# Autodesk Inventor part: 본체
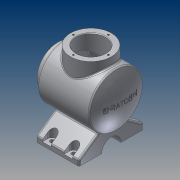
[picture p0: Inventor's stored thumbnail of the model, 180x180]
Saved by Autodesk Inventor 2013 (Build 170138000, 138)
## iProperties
Created: 2017-04
Part Number: 본체
Material: 알루미늄 6061
Document SubType Name: Modeling
Designer: Administrator
Density: 2.71 g/cm^3
Mass: 1670.26 g
Surface Area: 1068.05 cm^2
Volume: 616.331 cm^3
Author: Administrator
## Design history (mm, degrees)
sketch "스케치1"
  geometry: L1 (-62, 82)-(58, 82); L2 (-50, 132)-(46.336, 132); L3 (-50, 132)-(-50, 120); L4 (-50, 120)-(-62, 120); L5 (-62, 120)-(-62, 82); L6 (39.916, 122)-(-40, 122); L7 (-62, 109)-(-40, 109); L8 (-40, 122)-(-40, 109); A1 r 113 centre (-55, 82) between (58, 82) and (46.336, 132); A2 r 103 centre (-55, 82) between (48, 82) and (39.916, 122); 1 further point
  constraints: 16 end point, 4 point on circle, 3 perpendicular, 3 point on line, 2 centre point, 2 parallel, 1 horizontal
  dimensions: "d1" = 120 distance of L1.start L1.end; "d3" = 58 horizontal distance of point (0, 0) L1.end; "d5" = 113 radius of A1; "d6" = 82 vertical distance of point (0, 0) L1.end; "d7" = 100 diameter of L2 L1; "d8" = 108 horizontal distance of L2.start L1.end; "d9" = 76 diameter of L4 L1; "d10" = 10 distance between parallel lines of L6 L2; "d12" = 10 radial gap between concentric circles of A1 A2; "d13" = 54 diameter of L7 L1; "d14" = 22 distance of L7.start L7.end
revolve "회전1" sketch "스케치1" stored, may be unused: angle "d15" = 90 deg
node "작업 평면1"
sketch "스케치2"
  geometry: L1 (-60, -82)-(-60, -72); L2 (60, -82)-(60, -72); L3 (0, -82)-(0, 0); L4 (-60, -72)-(-21.584, -45.101); L5 (60, -72)-(21.584, -45.101); L6 (-60, -82)-(-18, -82); L7 (60, -82)-(18, -82); C1 r 27 at (0, 0) reference; A1 r 50 centre (0, 0) between (-21.584, -45.101) and (21.584, -45.101) reference; A2 r 18 centre (0, -82) between (18, -82) and (-18, -82)
  constraints: 14 end point, 4 point on circle, 3 parallel, 2 horizontal alignment, 1 centre point, 1 coincident, 1 collinear, 1 perpendicular, 1 vertical, 2 other
  dimensions: "d18" = 120 distance of L1.start L2.start; "d20" = 55 deg angle of L1 L4; "d21" = 18 radius of A2; "d98" = 10 distance of L2.start L2.end
extrude "돌출1" join sketch "스케치2" distance "d22" = 80; taper "d23" = 0 deg
node "작업 평면2"
sketch "스케치3"
  geometry: L1 (-38, 60)-(42, 60) reference; L2 (42, 60)-(42, 16.971) reference; L3 (42, 16.971)-(-38, 16.971) reference; L4 (-38, 16.971)-(-38, 60) reference; L5 (42, -60)-(-38, -60) reference; L6 (-38, -60)-(-38, -16.971) reference; L7 (-38, -16.971)-(42, -16.971) reference; L8 (42, -16.971)-(42, -60) reference; L9 (30, 50)-(30, 60); L10 (14, 50)-(14, 60); A1 r 8 centre (22, 50) between (30, 50) and (14, 50); 1 further point
  constraints: 4 end point, 2 parallel, 2 point on circle, 2 point on line, 2 tangent, 1 centre point
  dimensions: "d25" = 8 radius of A1; "d27" = 20 distance from line of A1.centre L2; "d28" = 10 distance from line of A1.centre L1
extrude "돌출2" cut sketch "스케치3" stored distance "d29" = 80; taper "d30" = 0 deg
hole "구멍1" diameter "d36" = 8; stored, may be unused: countersink angle "d40" = 90 deg, drill point angle "d42" = 118 deg; dims "d34" = 10, "d35" = 10, "d37" = 6, "d38" = 4, "d39" = 2, "d41" = 8
node "작업 평면3"
sketch "스케치4"
  geometry: C1 r 38 at (0, 0); 1 further point
  constraints: 1 centre point, 1 coincident
  dimensions: "d50" = 76 diameter of C1
extrude "돌출3" join sketch "스케치4" stored distance "d52" = 80; taper "d53" = 0 deg
hole "구멍2" diameter "d56" = 54; stored, may be unused: countersink angle "d60" = 90 deg, drill point angle "d62" = 0 deg; dims "d54" = 10, "d55" = 10, "d57" = 6, "d58" = 4, "d59" = 2, "d61" = 58.25
node "작업 평면4"
sketch "스케치5"
  geometry: C1 r 50 at (0, 0) reference; 2 further points
  constraints: 1 coincident, 1 other
feature "엠보싱1" sketch "스케치5" dims "d1" = 120, "d3" = 58, "d5" = 113, "d6" = 82, "d7" = 100, "d8" = 108, "d9" = 76, "d10" = 10, "d12" = 10, "d13" = 54, "d14" = 22, "d63" = 0.5, "d64" = 0
sketch "스케치6" dims "d65" = 65
  geometry: C1 r 38 at (0, 0) reference; C2 r 27 at (0, 0) reference; 3 further points
  constraints: 2 vertical alignment, 1 coincident, 2 other
hole "구멍3" sketch "스케치6" at (0, 32.5) diameter "d67" = 3.242; stored, may be unused: countersink angle "d71" = 90 deg, drill point angle "d73" = 118 deg; dims "d68" = 8, "d69" = 4, "d70" = 2, "d72" = 10
sketch "스케치7" dims "d77" = 65
  geometry: C1 r 27 at (0, 0) reference; C2 r 38 at (0, 0) reference; 2 further points
  constraints: 2 vertical alignment, 1 coincident, 2 other
hole "구멍4" sketch "스케치7" at (0, 32.5) diameter "d79" = 3.242; stored, may be unused: countersink angle "d83" = 90 deg, drill point angle "d85" = 118 deg; dims "d80" = 8, "d81" = 4, "d82" = 2, "d84" = 10
fillet "모깎기1" dims "d93" = 3
chamfer "모따기1" distance "d94" = 1; stored, may be unused: second distance "d95" = 2, angle "d96" = 45 deg
fillet "모깎기2" dims "d97" = 3
node "솔리드1"
pattern_linear "직사각형 패턴1" dims "d33" = 40
mirror "대칭1"
pattern_linear "직사각형 패턴2" dims "d45" = 40
pattern_circular "원형 패턴1" dims angle "d75" = 360 deg
pattern_circular "원형 패턴2" dims angle "d87" = 360 deg
node "절단 모서리 투영1"
node "절단 모서리 투영2"
other parameters: "d16" = -8, "d24" = 6, "d49" = 147, "d89" = 0.5, "d90" = 2, "d91" = 0
